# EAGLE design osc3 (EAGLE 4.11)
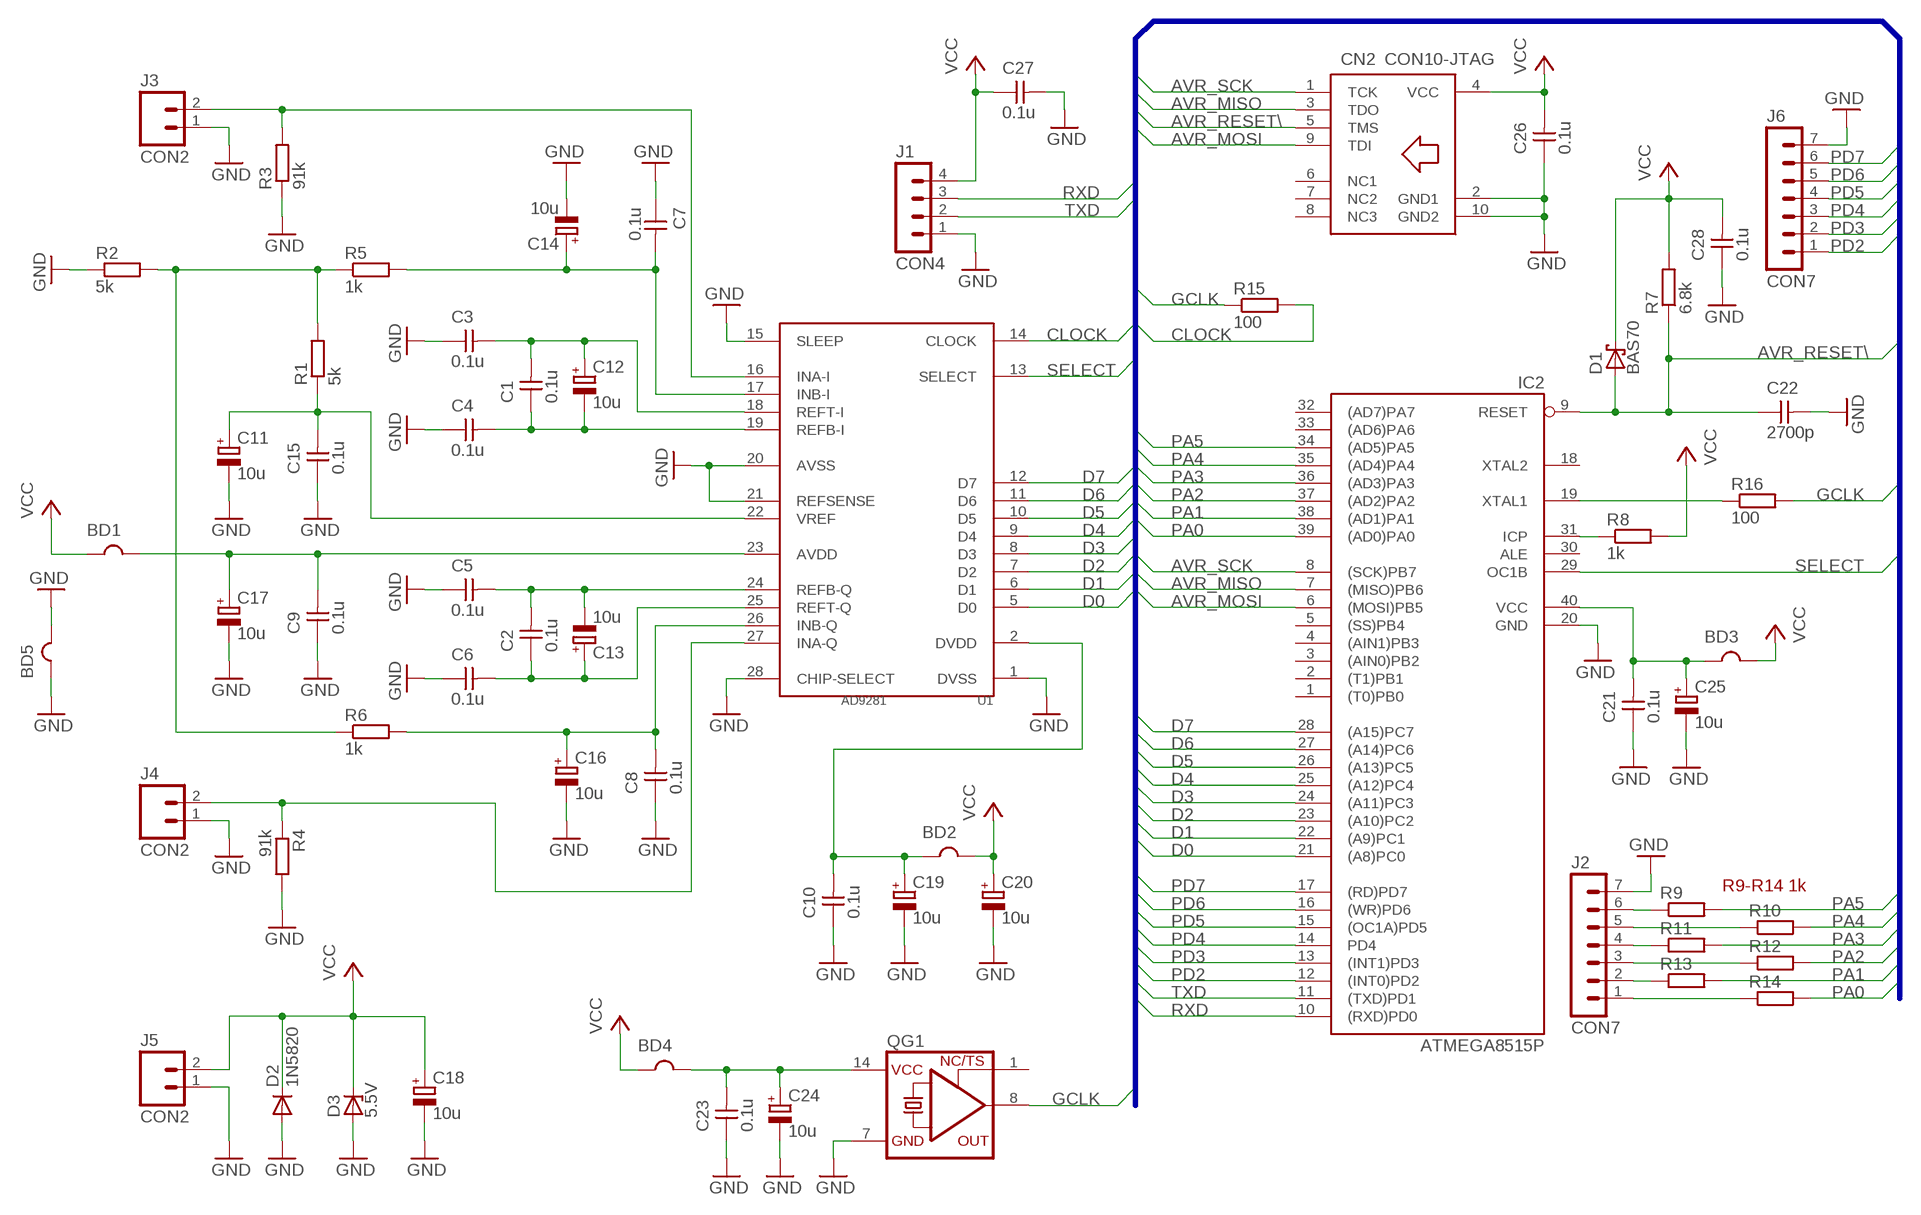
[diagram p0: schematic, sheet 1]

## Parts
BD1  FERRITE-BEAD-AXIAL-10  [BEAD-AXIAL-10]
BD2  FERRITE-BEAD-AXIAL-10  [BEAD-AXIAL-10]
BD3  FERRITE-BEAD-AXIAL-10  [BEAD-AXIAL-10]
BD4  FERRITE-BEAD-AXIAL-10  [BEAD-AXIAL-10]
BD5  FERRITE-BEAD-AXIAL-10  [BEAD-AXIAL-10]
C1  0.1u  0805-CTOP  [C0805-PAC-TOP]
C2  0.1u  0805-CTOP  [C0805-PAC-TOP]
C3  0.1u  0805-CTOP  [C0805-PAC-TOP]
C4  0.1u  0805-CTOP  [C0805-PAC-TOP]
C5  0.1u  0805-CTOP  [C0805-PAC-TOP]
C6  0.1u  0805-CTOP  [C0805-PAC-TOP]
C7  0.1u  0805-CTOP  [C0805-PAC-TOP]
C8  0.1u  0805-CTOP  [C0805-PAC-TOP]
C9  0.1u  0805-CTOP  [C0805-PAC-TOP]
C10  0.1u  0805-CTOP  [C0805-PAC-TOP]
C11  10u  CT3528-TOP  [CT3528]
C12  10u  CT3528-TOP  [CT3528]
C13  10u  CT3528-TOP  [CT3528]
C14  10u  CT3528-TOP  [CT3528]
C15  0.1u  0805-CTOP  [C0805-PAC-TOP]
C16  10u  CT3528-TOP  [CT3528]
C17  10u  CT3528-TOP  [CT3528]
C18  10u  CT3528-TOP  [CT3528]
C19  10u  CT3528-TOP  [CT3528]
C20  10u  CT3528-TOP  [CT3528]
C21  0.1u  0805-CTOP  [C0805-PAC-TOP]
C22  2700p  0805-CTOP  [C0805-PAC-TOP]
C23  0.1u  0805-CTOP  [C0805-PAC-TOP]
C24  10u  CT3528-TOP  [CT3528]
C25  10u  CT3528-TOP  [CT3528]
C26  0.1u  0805-CTOP  [C0805-PAC-TOP]
C27  0.1u  0805-CTOP  [C0805-PAC-TOP]
C28  0.1u  0805-CTOP  [C0805-PAC-TOP]
CN2  CON10-JTAG  [CON10-JTAG]
D1  BAS70  [SOT23]
D2  1N5820  DIODE-DO201-15  [DO201-15]
D3  5.5V  ZENER-DIODEDO41Z10  [DO41Z10]
IC2  ATMEGA8515P  AT90S8515P  [DIL40]
J1  CON4  [CON4]
J2  CON7  [CON7]
J3  CON2  [CON2]
J4  CON2  [CON2]
J5  CON2  [CON2]
J6  CON7  [CON7]
QG1  XO-14  [DIL14S]
R1  5k  0805-RTOP  [R0805-PAC-TOP]
R2  5k  0805-RTOP  [R0805-PAC-TOP]
R3  91k  0805-RTOP  [R0805-PAC-TOP]
R4  91k  0805-RTOP  [R0805-PAC-TOP]
R5  1k  0805-RTOP  [R0805-PAC-TOP]
R6  1k  0805-RTOP  [R0805-PAC-TOP]
R7  6.8k  0805-RTOP  [R0805-PAC-TOP]
R8  1k  0805-RTOP  [R0805-PAC-TOP]
R9  0805-RTOP  [R0805-PAC-TOP]
R10  0805-RTOP  [R0805-PAC-TOP]
R11  0805-RTOP  [R0805-PAC-TOP]
R12  0805-RTOP  [R0805-PAC-TOP]
R13  0805-RTOP  [R0805-PAC-TOP]
R14  0805-RTOP  [R0805-PAC-TOP]
R15  100  0805-RTOP  [R0805-PAC-TOP]
R16  100  0805-RTOP  [R0805-PAC-TOP]
U1  AD9281  [SSOP-28]

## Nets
AVR_MISO: CN2.3(TDO) IC2.7((MISO)PB6)
AVR_MOSI: CN2.9(TDI) IC2.6((MOSI)PB5)
AVR_RESET\: C22.P$1 CN2.5(TMS) D1.1(A) IC2.9(RESET) R7.P$1
AVR_SCK: CN2.1(TCK) IC2.8((SCK)PB7)
CLOCK: R15.P$2 U1.14(CLOCK)
D0: IC2.21((A8)PC0) U1.5(D0)
D1: IC2.22((A9)PC1) U1.6(D1)
D2: IC2.23((A10)PC2) U1.7(D2)
D3: IC2.24((A11)PC3) U1.8(D3)
D4: IC2.25((A12)PC4) U1.9(D4)
D5: IC2.26((A13)PC5) U1.10(D5)
D6: IC2.27((A14)PC6) U1.11(D6)
D7: IC2.28((A15)PC7) U1.12(D7)
GCLK: QG1.8(OUT) R15.P$1 R16.P$2
GND: BD5.1 BD5.2 C3.P$1 C4.P$1 C5.P$1 C6.P$1 C7.P$1 C8.P$1 C9.P$1 C10.P$1 C11.- C14.- C15.P$1 C16.- C17.- C18.- C19.- C20.- C21.P$1 C22.P$2 C23.P$1 C24.- C25.- C26.P$1 C27.P$2 C28.P$1 CN2.2(GND1) CN2.10(GND2) D2.A D3.A IC2.20(GND) J1.1 J2.7 J3.1 J4.1 J5.1 J6.7 QG1.7(GND) R2.P$1 R3.P$1 R4.P$2 U1.1(DVSS) U1.15(SLEEP) U1.20(AVSS) U1.21(REFSENSE) U1.28(CHIP-SELECT)
N$1: C1.P$1 C4.P$2 C12.- U1.19(REFB-I)
N$2: C1.P$2 C3.P$2 C12.+ U1.18(REFT-I)
N$3: C2.P$2 C5.P$2 C13.- U1.24(REFB-Q)
N$4: C2.P$1 C6.P$2 C13.+ U1.25(REFT-Q)
N$5: BD1.2 C9.P$2 C17.+ U1.23(AVDD)
N$6: C11.+ C15.P$2 R1.P$1 U1.22(VREF)
N$7: R1.P$2 R2.P$2 R5.P$1 R6.P$1
N$8: J3.2 R3.P$2 U1.16(INA-I)
N$9: J4.2 R4.P$1 U1.27(INA-Q)
N$10: C7.P$2 C14.+ R5.P$2 U1.17(INB-I)
N$11: C8.P$2 C16.+ R6.P$2 U1.26(INB-Q)
N$12: IC2.19(XTAL1) R16.P$1
N$13: BD2.1 C10.P$2 C19.+ U1.2(DVDD)
N$14: IC2.31(ICP) R8.P$1
N$15: J2.6 R9.P$1
N$16: J2.5 R10.P$1
N$17: J2.4 R11.P$1
N$18: J2.3 R12.P$1
N$19: J2.2 R13.P$1
N$20: BD3.1 C21.P$2 C25.+ IC2.40(VCC)
N$21: J2.1 R14.P$1
N$22: BD4.2 C23.P$2 C24.+ QG1.14(VCC)
PA0: IC2.39((AD0)PA0) R14.P$2
PA1: IC2.38((AD1)PA1) R13.P$2
PA2: IC2.37((AD2)PA2) R12.P$2
PA3: IC2.36((AD3)PA3) R11.P$2
PA4: IC2.35((AD4)PA4) R10.P$2
PA5: IC2.34((AD5)PA5) R9.P$2
PD2: IC2.12((INT0)PD2) J6.1
PD3: IC2.13((INT1)PD3) J6.2
PD4: IC2.14(PD4) J6.3
PD5: IC2.15((OC1A)PD5) J6.4
PD6: IC2.16((WR)PD6) J6.5
PD7: IC2.17((RD)PD7) J6.6
RXD: IC2.10((RXD)PD0) J1.3
SELECT: IC2.29(OC1B) U1.13(SELECT)
TXD: IC2.11((TXD)PD1) J1.2
VCC: BD1.1 BD2.2 BD3.2 BD4.1 C18.+ C20.+ C26.P$2 C27.P$1 C28.P$2 CN2.4(VCC) D1.3(C) D2.C D3.C J1.4 J5.2 R7.P$2 R8.P$2
Unconnected: CN2.6(NC1) CN2.7(NC2) CN2.8(NC3) IC2.1((T0)PB0) IC2.2((T1)PB1) IC2.3((AIN0)PB2) IC2.4((AIN1)PB3) IC2.5((SS)PB4) IC2.18(XTAL2) IC2.30(ALE) IC2.32((AD7)PA7) IC2.33((AD6)PA6) QG1.1(TS)

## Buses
GCLK,PD[2..7],PA[0..5],D[0..7],SLEEP,CLOCK,SELECT,AVR_SCK,AVR_MISO,AVR_RESET\,AVR_MOSI,TXD,RXD

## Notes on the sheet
- R9-R14 1k

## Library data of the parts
BD1-BD5 = _custom:FERRITE-BEAD
C1-C10 C15 C21-C23 C26-C28 = _custom:0805-C
C11-C14 C16-C20 C24 C25 = _custom:CT3528: Tantalum Capacitor, Code Size B (3528)
CN2 = _custom:CON10-JTAG
D1 = diode:BAS70: Silicon Schottky Diodes
D2 = diode:DIODE-: DIODE
D3 = diode:ZENER-DIODE: Z-Diode
IC2 = atmel:AT90S8515P: MICROCONTROLLER 8 Kbytes FLASH 512 bytes SRAM 512 bytes EEPROM UART
J1 = _custom:CON4
J2 J6 = _custom:CON7
J3-J5 = _custom:CON2
QG1 = crystal:XO-: CRYSTAL
R1-R16 = _custom:0805-R
U1 = _custom:AD9281

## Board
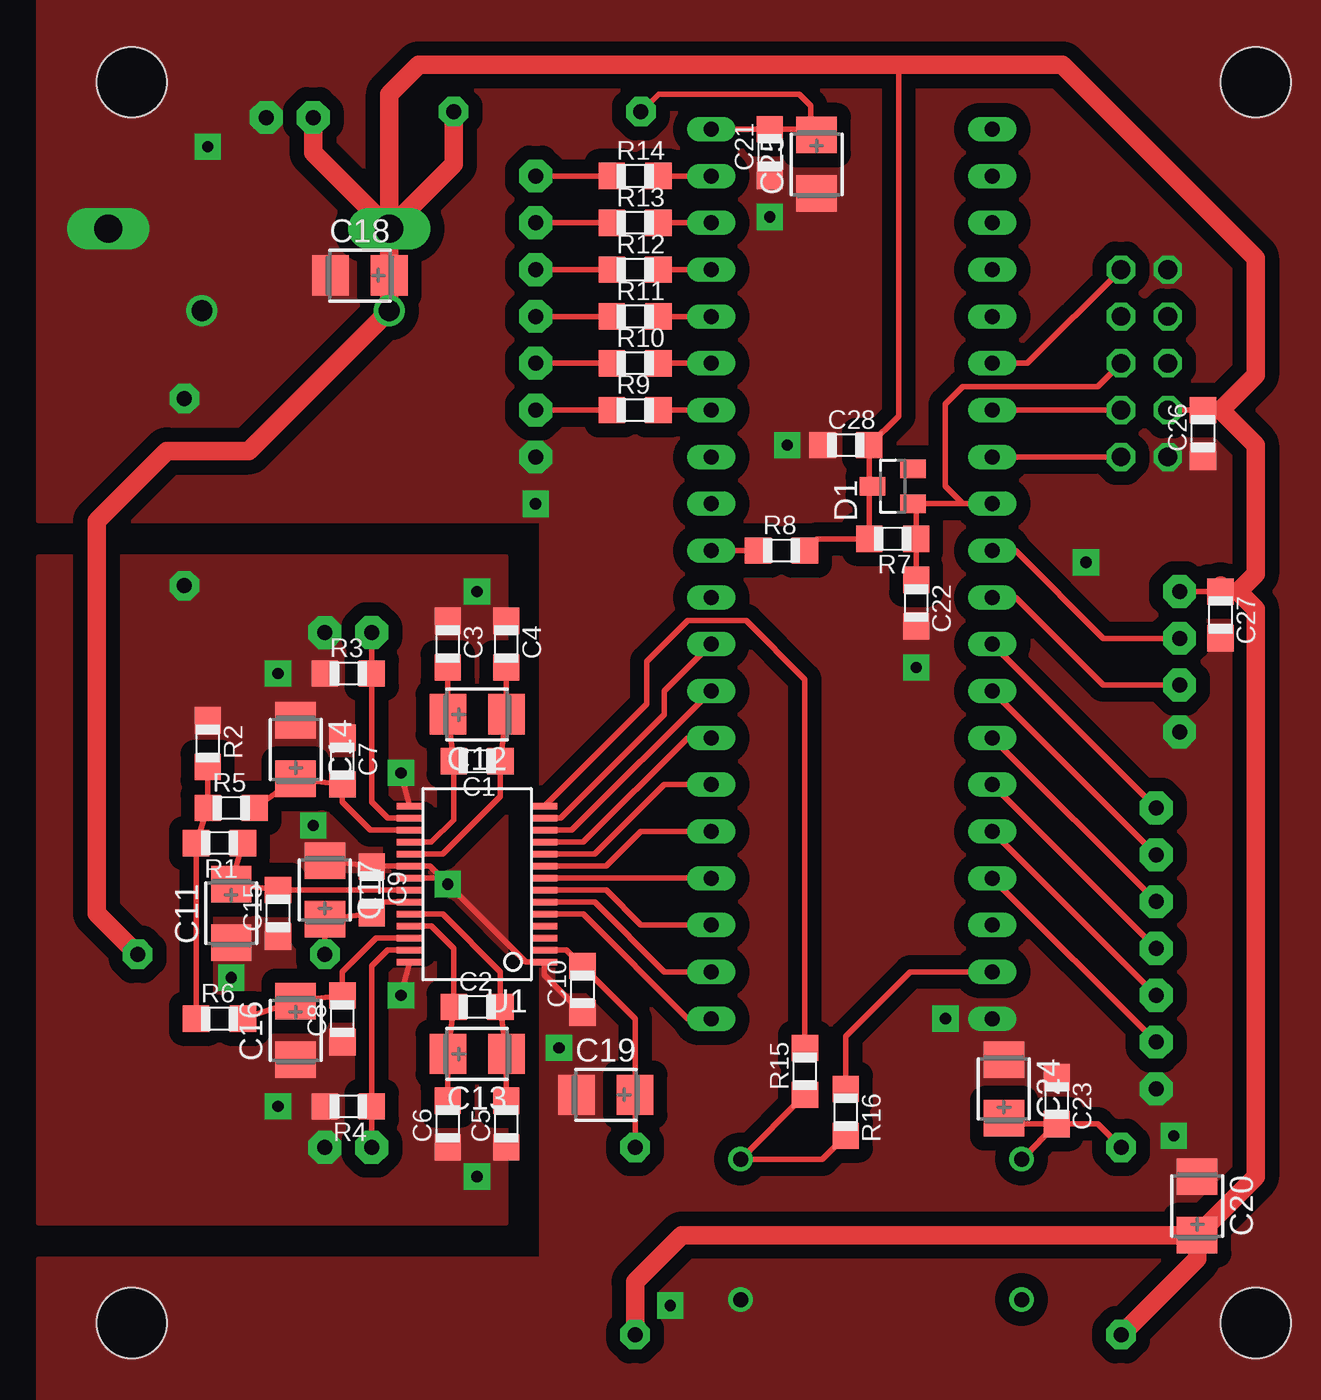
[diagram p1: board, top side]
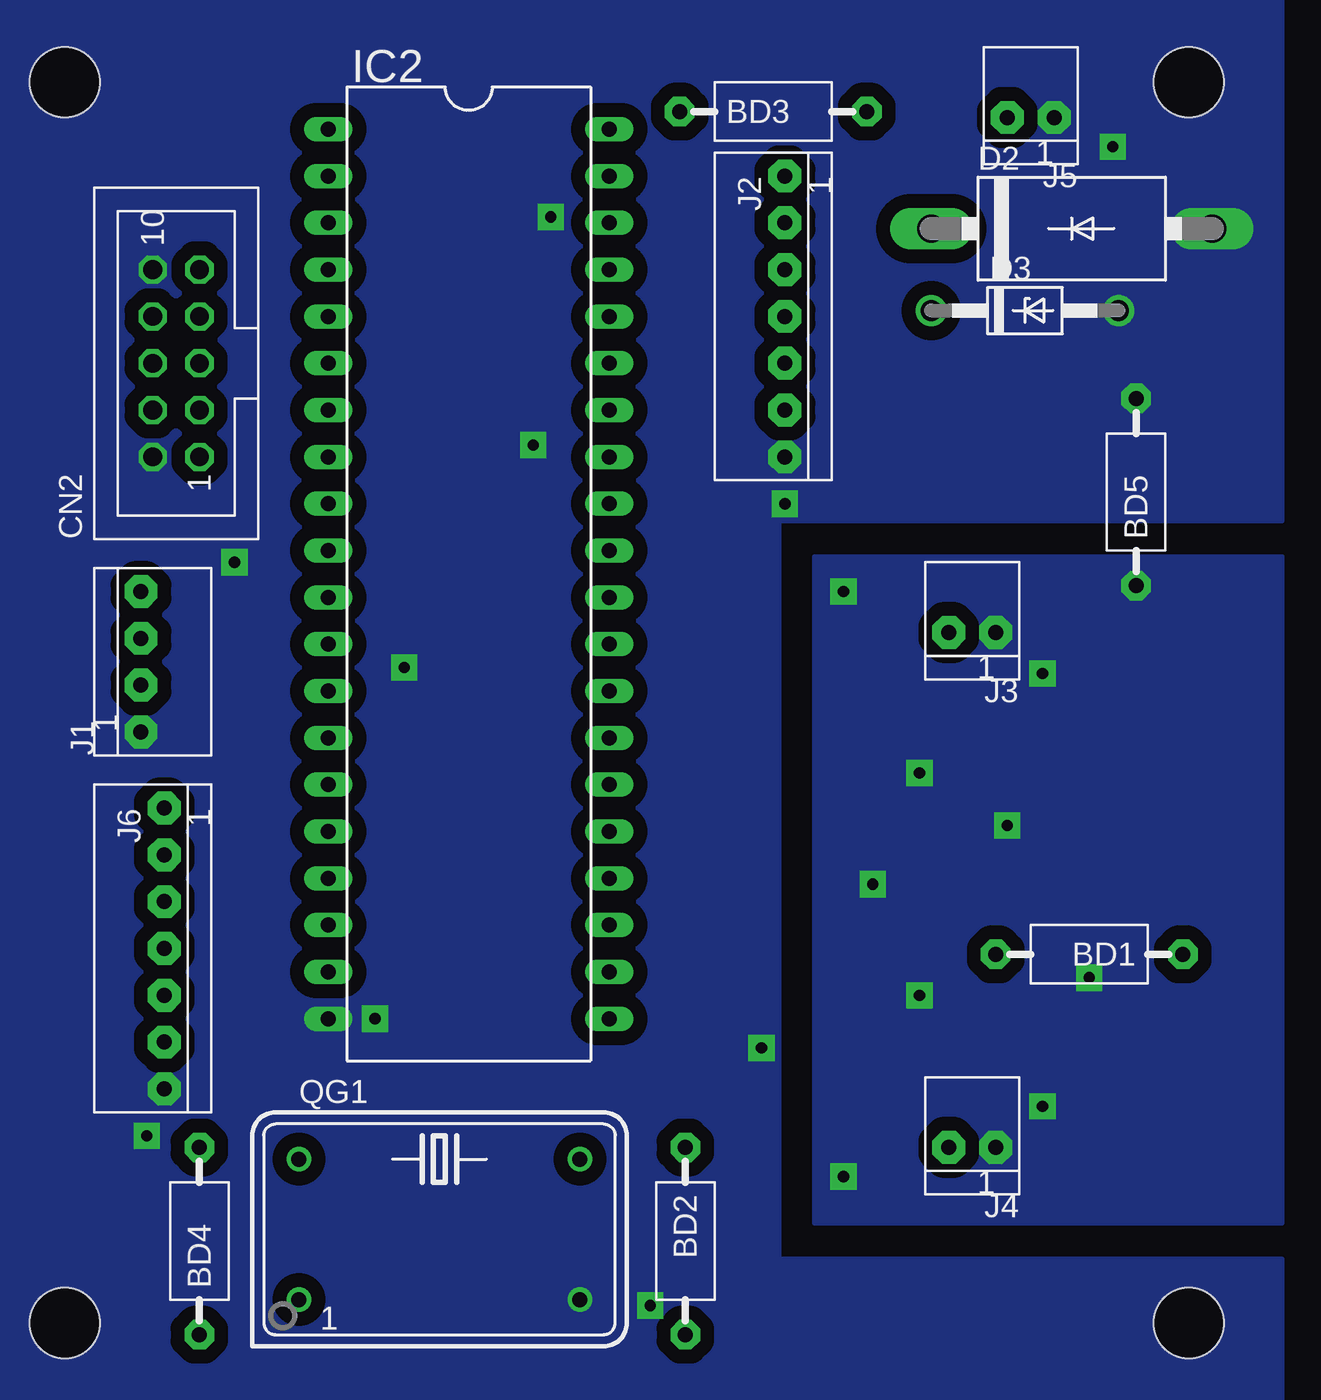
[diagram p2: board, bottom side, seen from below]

No outline drawn. Coordinates in mm, seen from the top.
Copper layers (1*16): Top 0.035mm / dielectric 1.5mm / Bottom 0.035mm
Design rules "default": minimum track width 10mil, minimum drill 24mil, track to track 30mil, track to pad 30mil, pad to pad 8mil, via to via 8mil, smd to smd 8mil, copper to edge 0mil, drill to drill 8mil, minimum pad ring 10mil, minimum via ring 8mil, stop-mask expansion 4mil, vias tented up to drill 0mil, thermal gap 10mil
Holes 3.81 mm at 66.04,72.39 66.04,5.08 5.08,5.08 5.08,72.39

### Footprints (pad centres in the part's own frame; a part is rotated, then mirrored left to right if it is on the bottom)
BEAD-AXIAL-10 = drill 0.813 pad 1.6 octagon: 1 -5.08,0; 2 5.08,0
C0805-PAC-TOP = smd 1.422 x 1.422: P$1 -1.27,0; P$2 1.27,0
CT3528 = smd 1.981 x 2.184: + 1.587,0; - -1.587,0
CON10-JTAG = drill 1.016 octagon: 1 -5.08,-1.27; 2 -5.08,1.27; 3 -2.54,-1.27; 4 -2.54,1.27; 5 0,-1.27; 6 0,1.27; 7 2.54,-1.27; 8 2.54,1.27; 9 5.08,-1.27; 10 5.08,1.27
SOT23 = smd 1 x 1.4: 1 -0.95,-1.1; 2 0.95,-1.1; 3 0,1.1
DO201-15 = drill 1.499 long: A 7.62,0; C -7.62,0
DO41Z10 = drill 1.118 round: A 5.08,0; C -5.08,0
DIL40 = drill 0.813 long: 1 -24.13,-7.62; 2 -21.59,-7.62; 3 -19.05,-7.62; 4 -16.51,-7.62; 5 -13.97,-7.62; 6 -11.43,-7.62; 7 -8.89,-7.62; 8 -6.35,-7.62; 9 -3.81,-7.62; 10 -1.27,-7.62; 11 1.27,-7.62; 12 3.81,-7.62; 13 6.35,-7.62; 14 8.89,-7.62; 15 11.43,-7.62; 16 13.97,-7.62; 17 16.51,-7.62; 18 19.05,-7.62; 19 21.59,-7.62; 20 24.13,-7.62; 21 24.13,7.62; 22 21.59,7.62; 23 19.05,7.62; 24 16.51,7.62; 25 13.97,7.62; 26 11.43,7.62; 27 8.89,7.62; 28 6.35,7.62; 29 3.81,7.62; 30 1.27,7.62; 31 -1.27,7.62; 32 -3.81,7.62; 33 -6.35,7.62; 34 -8.89,7.62; 35 -11.43,7.62; 36 -13.97,7.62; 37 -16.51,7.62; 38 -19.05,7.62; 39 -21.59,7.62; 40 -24.13,7.62
CON4 = drill 0.813 pad 1.778 octagon: 1 -3.81,-2.54; 2 -1.27,-2.54; 3 1.27,-2.54; 4 3.81,-2.54
CON7 = drill 0.813 pad 1.778 octagon: 1 -7.62,-2.54; 2 -5.08,-2.54; 3 -2.54,-2.54; 4 0,-2.54; 5 2.54,-2.54; 6 5.08,-2.54; 7 7.62,-2.54
CON2 = drill 0.813 pad 1.778 octagon: 1 -1.27,-2.54; 2 1.27,-2.54
DIL14S = drill 0.813 round: 1 -7.62,-3.81; 7 7.62,-3.81; 8 7.62,3.81; 14 -7.62,3.81
R0805-PAC-TOP = smd 1.422 x 1.422: P$1 -1.27,0; P$2 1.27,0
SSOP-28 = smd 0.348 x 1.397: 1 -4.225,-3.656; 2 -3.575,-3.656; 3 -2.925,-3.656; 4 -2.275,-3.656; 5 -1.625,-3.656; 6 -0.975,-3.656; 7 -0.325,-3.656; 8 0.325,-3.656; 9 0.975,-3.656; 10 1.625,-3.656; 11 2.275,-3.656; 12 2.925,-3.656; 13 3.575,-3.656; 14 4.225,-3.656; 15 4.225,3.656; 16 3.575,3.656; 17 2.925,3.656; 18 2.275,3.656; 19 1.625,3.656; 20 0.975,3.656; 21 0.325,3.656; 22 -0.325,3.656; 23 -0.975,3.656; 24 -1.625,3.656; 25 -2.275,3.656; 26 -2.925,3.656; 27 -3.575,3.656; 28 -4.225,3.656

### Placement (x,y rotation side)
BD1  10.48,25.08 180 bottom
BD2  32.38,9.53 270 bottom
BD3  27.62,70.8 0 bottom
BD4  58.74,9.53 90 bottom
BD5  7.94,50.16 90 bottom
C1  23.81,35.56 180 top
C2  23.81,22.23 0 top
C3  22.23,41.91 270 top
C4  25.4,41.91 270 top
C5  25.4,15.88 90 top
C6  22.23,15.88 90 top
C7  16.51,35.56 270 top
C8  16.51,21.59 90 top
C9  18.1,28.57 270 top
C10  29.53,23.18 90 top
C11  10.48,27.3 90 top
C12  23.81,38.1 180 top
C13  23.81,19.68 180 top
C14  13.97,36.2 270 top
C15  13.02,27.3 90 top
C16  13.97,20.95 90 top
C17  15.56,28.57 270 top
C18  17.46,61.91 0 top
C19  30.8,17.46 0 top
C20  62.87,11.43 270 top
C21  39.69,68.58 90 top
C22  47.62,44.13 270 top
C23  55.24,17.14 270 top
C24  52.39,17.78 270 top
C25  42.23,67.94 90 top
C26  63.18,53.34 90 top
C27  64.14,43.5 270 top
C28  43.81,52.7 0 top
CN2  60.01,57.15 90 bottom
D1  46.35,50.48 90 top
D2  11.43,64.45 0 bottom
D3  13.97,60.01 0 bottom
IC2  44.13,45.72 270 bottom
J1  64.45,40.96 90 bottom
J2  24.45,59.69 270 bottom
J3  16.83,40.01 180 bottom
J4  16.83,12.06 180 bottom
J5  13.65,67.94 180 bottom
J6  58.1,25.4 270 bottom
QG1  45.72,10.16 0 bottom
R1  9.84,31.11 180 top
R2  9.21,36.51 270 top
R3  16.83,40.32 0 top
R4  16.83,16.83 180 top
R5  10.48,33.02 0 top
R6  9.84,21.59 0 top
R7  46.35,47.62 180 top
R8  40.32,46.99 0 top
R9  32.38,54.61 0 top
R10  32.38,57.15 0 top
R11  32.38,59.69 0 top
R12  32.38,62.23 0 top
R13  32.38,64.77 0 top
R14  32.38,67.31 0 top
R15  41.59,18.73 90 top
R16  43.81,16.51 270 top
U1  23.81,28.89 90 top

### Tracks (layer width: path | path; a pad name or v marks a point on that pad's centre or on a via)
AVR_MISO
  Top 0.305: IC2.7 CN2.3
AVR_MOSI
  Top 0.305: IC2.6 53.66,57.15 CN2.9
AVR_RESET\
  Top 0.305: CN2.5 57.47,55.88 50.16,55.88 49.21,54.93 49.21,50.48 50.16,49.53 | 50.16,49.53 IC2.9 | 50.16,49.53 D1.1 47.62,49.36 R7.P$1 C22.P$1
AVR_SCK
  Top 0.305: IC2.8 CN2.1
CLOCK
  Top 0.305: U1.14 33.02,38.67 33.02,40.96 35.24,43.18 38.42,43.18 41.59,40.01 R15.P$2
D0
  Top 0.305: U1.5 29.57,27.27 35.24,21.59 IC2.21
D1
  Top 0.305: U1.6 30.18,27.92 33.97,24.13 IC2.22
D2
  Top 0.305: U1.7 30.8,28.57 32.7,26.67 IC2.23
D3
  Top 0.305: U1.8 IC2.24
D4
  Top 0.305: U1.9 30.82,29.87 32.7,31.75 IC2.25
D5
  Top 0.305: U1.10 30.2,30.52 33.97,34.29 IC2.26
D6
  Top 0.305: U1.11 29.58,31.17 35.24,36.83 IC2.27
D7
  Top 0.305: U1.12 28.96,31.82 IC2.28
GCLK
  Top 0.305: R15.P$1 QG1.8 42.55,13.97 R16.P$2
GND  (via drill 0.61 pad 1.42)
  Top 0.305: C17.- C9.P$1 | C9.P$1 18.12,29.87 | v22.23,28.89 21.25,29.87 U1.20 18.1,29.87 C9.P$1 | U1.21 21.9,29.22 v22.23,28.89 | U1.15 v19.68,34.92 | U1.28 v19.68,22.86 | v22.23,28.89 26.45,24.67 U1.1 27.47,23.97 C10.P$1
  other vias: 14.92,32.07 23.81,13.02 23.81,44.77 10.48,23.81 9.21,68.9 13.02,16.83 13.02,40.32 26.99,49.53 34.29,6.03 28.26,20 39.69,65.09 40.64,52.7 49.21,21.59 56.83,46.35 61.59,15.24 47.62,40.64
  pour Bottom (no thermals): 0,46.67 25.4,46.67 25.4,10.48 0,10.48
  pour Top (no thermals): 0,46.67 25.4,46.67 25.4,10.48 0,10.48
  pour Top (no thermals): 0,77.47 71.12,77.47 71.12,0 0,0 0,8.57 27.3,8.57 27.3,7.94 27.3,48.58 0,48.58
  pour Bottom (no thermals): 0,77.47 71.12,77.47 71.12,0 0,0 0,8.57 27.3,8.57 27.3,48.58 0,48.58
N$1
  Top 0.305: U1.19 21.95,30.52 25.08,33.66 C1.P$1 C12.- C4.P$2
N$2
  Top 0.305: U1.18 21.32,31.17 22.54,32.38 C1.P$2 C12.+ C3.P$2
N$3
  Top 0.305: U1.24 21.95,27.27 25.08,24.13 C2.P$2 C13.- C5.P$2
N$4
  Top 0.305: U1.25 21.32,26.62 22.54,25.4 C2.P$1 C13.+ C6.P$2
N$5
  Top 0.305: U1.23 18.71,27.92 C9.P$2 C17.+ BD1.2
N$6
  Top 0.305: U1.22 C15.P$2 C11.+ R1.P$1
N$7
  Top 0.305: R6.P$1 R1.P$2 R5.P$1 R2.P$2
N$8
  Top 0.305: U1.16 18.97,32.47 18.1,33.34 R3.P$2 J3.2
N$9
  Top 0.305: U1.27 18.97,25.32 18.1,24.45 R4.P$1 J4.2
N$10
  Top 0.305: U1.17 18.03,31.82 16.51,33.34 C7.P$2 C14.+ R5.P$2
N$11
  Top 0.305: U1.26 18.35,25.97 16.51,24.13 C8.P$2 C16.+ R6.P$2
N$12
  Top 0.305: IC2.19 47.31,24.13 43.81,20.64 R16.P$1
N$13
  Top 0.305: BD2.1 C19.+ 32.38,21.59 C10.P$2 28.66,25.32 U1.2
N$14
  Top 0.305: IC2.31 R8.P$1
N$15
  Top 0.305: J2.6 R9.P$1
N$16
  Top 0.305: J2.5 R10.P$1
N$17
  Top 0.305: J2.4 R11.P$1
N$18
  Top 0.305: J2.3 R12.P$1
N$19
  Top 0.305: J2.2 R13.P$1
N$20
  Top 0.305: IC2.40 C21.P$2 41.91,69.85 | 41.91,69.85 C25.+ | BD3.1 33.66,71.75 41.27,71.75 41.91,71.12 41.91,69.85
N$21
  Top 0.305: J2.1 R14.P$1
N$22
  Top 0.305: C23.P$2 57.47,15.88 BD4.2 | C24.+ 52.7,15.88 C23.P$2 | C23.P$2 QG1.14
PA0
  Top 0.305: R14.P$2 IC2.39
PA1
  Top 0.305: R13.P$2 IC2.38
PA2
  Top 0.305: R12.P$2 IC2.37
PA3
  Top 0.305: R11.P$2 IC2.36
PA4
  Top 0.305: R10.P$2 IC2.35
PA5
  Top 0.305: R9.P$2 IC2.34
PD2
  Top 0.305: J6.1 IC2.12
PD3
  Top 0.305: J6.2 IC2.13
PD4
  Top 0.305: J6.3 IC2.14
PD5
  Top 0.305: J6.4 IC2.15
PD6
  Top 0.305: J6.5 IC2.16
PD7
  Top 0.305: J6.6 IC2.17
RXD
  Top 0.305: IC2.10 53.02,46.99 57.78,42.23 J1.3
SELECT
  Top 0.305: U1.13 28.34,32.47 33.97,38.1 33.97,39.37 IC2.29
TXD
  Top 0.305: IC2.11 53.02,44.45 57.78,39.69 J1.2
VCC
  Top 0.305: R8.P$2 42.23,47.62 R7.P$2 45.09,50.31 D1.3 45.09,50.65 C28.P$2 46.67,54.29 46.67,73.34 | C26.P$2 CN2.4 | C27.P$1 J1.4
  Top 1.016: BD2.2 32.38,7.3 34.92,9.84 C20.+ | 64.14,54.61 66.04,52.7 66.04,45.72 65.09,44.77 | 64.14,54.61 C26.P$2 | 64.14,54.61 66.04,56.52 66.04,62.87 55.56,73.34 46.67,73.34 20.64,73.34 19.05,71.75 D2.C | 64.14,45.09 C27.P$1 65.09,44.77 | 65.09,44.77 66.04,43.81 66.04,13.02 C20.+ | BD1.1 3.17,27.3 3.17,48.58 6.99,52.39 11.43,52.39 D3.C C18.+ D2.C | J5.2 14.92,68.58 D2.C | D2.C 22.54,67.94 BD3.2 | C20.+ 62.87,8.57 BD4.1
